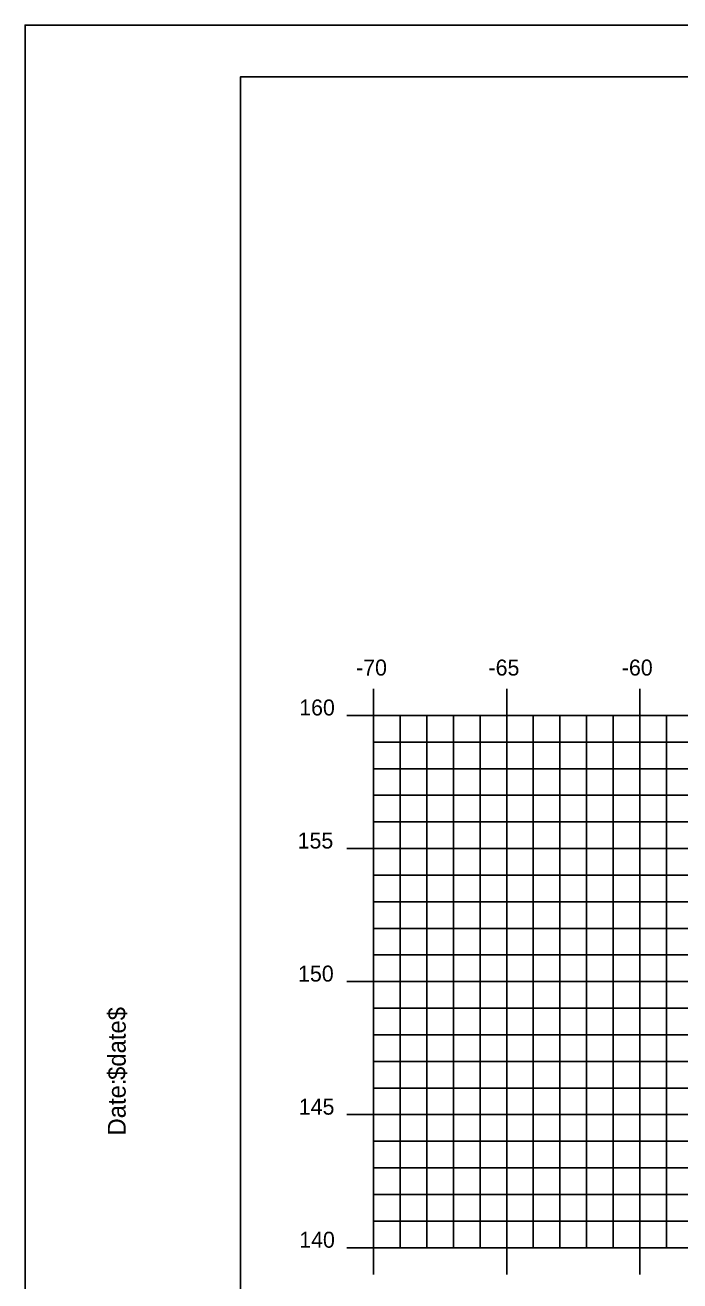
# Model space of a CAD drawing. Extents: x 1147190 to 1147360, y 608981 to 609091.
# Drawn here: x 1147189.85 to 1147214.45, y 609044.09 to 609091.28 of the extents above; entities that cross this region are included whole.
import ezdxf

# ---------------------------------------------------------------- set-up
doc = ezdxf.new("R2010")
doc.units = 0
for name, color, linetype in [('BORDER', 7, 'Continuous'), ('H_V ANNOTATION', 7, 'Continuous'), ('MAJOR', 7, 'Continuous'), ('MINOR', 7, 'Continuous'), ('PLOT BOUNDARY', 7, 'Continuous')]:
    doc.layers.add(name, color=color, linetype=linetype)

msp = doc.modelspace()

# ---------------------------------------------------------------- linework, layer by layer
at = {"layer": 'BORDER'}
msp.add_lwpolyline([(1147197.941, 608984.335), (1147357.941, 608984.335), (1147357.941, 609089.335), (1147197.941, 609089.335)], close=True, dxfattribs=at)
at = {"layer": 'MAJOR'}
for p, q in [((1147202.941, 609066.337), (1147202.941, 609065.335)), ((1147207.941, 609066.337), (1147207.941, 609065.335)), ((1147212.941, 609066.337), (1147212.941, 609065.335)), ((1147201.939, 609065.335), (1147202.941, 609065.335)), ((1147202.941, 609065.335), (1147342.941, 609065.335)), ((1147202.941, 609045.335), (1147202.941, 609065.335)), ((1147202.941, 609045.335), (1147202.941, 609065.335)), ((1147202.941, 609065.335), (1147342.941, 609065.335)), ((1147207.941, 609045.335), (1147207.941, 609065.335)), ((1147212.941, 609045.335), (1147212.941, 609065.335)), ((1147201.939, 609060.335), (1147202.941, 609060.335)), ((1147202.941, 609060.335), (1147342.941, 609060.335)), ((1147201.939, 609055.335), (1147202.941, 609055.335)), ((1147202.941, 609055.335), (1147342.941, 609055.335)), ((1147201.939, 609050.335), (1147202.941, 609050.335)), ((1147202.941, 609050.335), (1147342.941, 609050.335)), ((1147201.939, 609045.335), (1147202.941, 609045.335)), ((1147202.941, 609045.335), (1147342.941, 609045.335)), ((1147202.941, 609045.335), (1147342.941, 609045.335)), ((1147202.941, 609044.333), (1147202.941, 609045.335)), ((1147207.941, 609044.333), (1147207.941, 609045.335)), ((1147212.941, 609044.333), (1147212.941, 609045.335))]:
    msp.add_line(p, q, dxfattribs=at)
at = {"layer": 'MINOR'}
for p, q in [((1147203.941, 609045.335), (1147203.941, 609065.335)), ((1147204.941, 609045.335), (1147204.941, 609065.335)), ((1147205.941, 609045.335), (1147205.941, 609065.335)), ((1147206.941, 609045.335), (1147206.941, 609065.335)), ((1147208.941, 609045.335), (1147208.941, 609065.335)), ((1147209.941, 609045.335), (1147209.941, 609065.335)), ((1147210.941, 609045.335), (1147210.941, 609065.335)), ((1147211.941, 609045.335), (1147211.941, 609065.335)), ((1147213.941, 609045.335), (1147213.941, 609065.335)), ((1147202.941, 609064.335), (1147342.941, 609064.335)), ((1147202.941, 609064.335), (1147203.943, 609064.335)), ((1147202.941, 609063.335), (1147342.941, 609063.335)), ((1147202.941, 609063.335), (1147203.943, 609063.335)), ((1147202.941, 609062.335), (1147342.941, 609062.335)), ((1147202.941, 609062.335), (1147203.943, 609062.335)), ((1147202.941, 609061.335), (1147342.941, 609061.335)), ((1147202.941, 609061.335), (1147203.943, 609061.335)), ((1147202.941, 609059.335), (1147342.941, 609059.335)), ((1147202.941, 609059.335), (1147203.943, 609059.335)), ((1147202.941, 609058.335), (1147342.941, 609058.335)), ((1147202.941, 609058.335), (1147203.943, 609058.335)), ((1147202.941, 609057.335), (1147342.941, 609057.335)), ((1147202.941, 609057.335), (1147203.943, 609057.335)), ((1147202.941, 609056.335), (1147342.941, 609056.335)), ((1147202.941, 609056.335), (1147203.943, 609056.335)), ((1147202.941, 609054.335), (1147342.941, 609054.335)), ((1147202.941, 609054.335), (1147203.943, 609054.335)), ((1147202.941, 609053.335), (1147342.941, 609053.335)), ((1147202.941, 609053.335), (1147203.943, 609053.335)), ((1147202.941, 609052.335), (1147342.941, 609052.335)), ((1147202.941, 609052.335), (1147203.943, 609052.335)), ((1147202.941, 609051.335), (1147342.941, 609051.335)), ((1147202.941, 609051.335), (1147203.943, 609051.335)), ((1147202.941, 609049.335), (1147342.941, 609049.335)), ((1147202.941, 609049.335), (1147203.943, 609049.335)), ((1147202.941, 609048.335), (1147342.941, 609048.335)), ((1147202.941, 609048.335), (1147203.943, 609048.335)), ((1147202.941, 609047.335), (1147342.941, 609047.335)), ((1147202.941, 609047.335), (1147203.943, 609047.335)), ((1147202.941, 609046.335), (1147342.941, 609046.335)), ((1147202.941, 609046.335), (1147203.943, 609046.335))]:
    msp.add_line(p, q, dxfattribs=at)
at = {"layer": 'PLOT BOUNDARY'}
msp.add_lwpolyline([(1147189.848, 608981.276), (1147359.848, 608981.276), (1147359.848, 609091.276), (1147189.848, 609091.276)], close=True, dxfattribs=at)

# ---------------------------------------------------------------- texts
at = {"layer": 'BORDER'}
for s, p in [('$date$', (1147193.626, 609051.64)), ('Date:', (1147193.626, 609049.552))]:
    msp.add_text(s, height=0.6696, rotation=90, dxfattribs=at).set_placement(p)
at = {"layer": 'H_V ANNOTATION'}
for s, p in [('-70', (1147202.282, 609066.835)), ('-65', (1147207.259, 609066.835)), ('-60', (1147212.267, 609066.835)), ('160', (1147200.146, 609065.335)), ('155', (1147200.087, 609060.335)), ('150', (1147200.103, 609055.335)), ('145', (1147200.13, 609050.335)), ('140', (1147200.146, 609045.335))]:
    msp.add_text(s, height=0.6, dxfattribs=at).set_placement(p)
at = {"layer": 'MAJOR'}
msp.add_text('-', height=0.006, dxfattribs=at).set_placement((1147202.936, 609045.335))

doc.saveas('drawing.dxf')
